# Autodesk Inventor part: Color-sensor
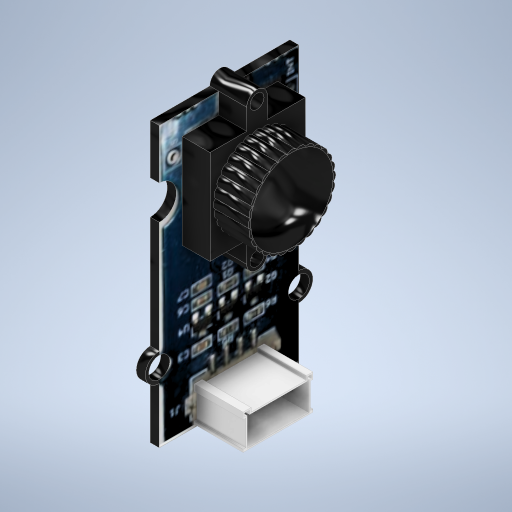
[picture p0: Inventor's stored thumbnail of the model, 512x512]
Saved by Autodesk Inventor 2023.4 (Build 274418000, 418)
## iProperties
Created: 2022-12
Part Number: Color-sensor
Material: Générique
Document SubType Name: Modeling
Designer: ecuenot
Density: 1 g/cm^3
Appearance: Noir
Author: ecuenot
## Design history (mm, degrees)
sketch "Esquisse1" dims "d48" = 3
  geometry: L1 (40, 0)-(40, -20); L2 (0, -20)-(0, 0); L3 (11.5, 0)-(12, 0); L4 (10, 0)-(8, 0); L5 (0, 0)-(8, 0); L6 (11.5, 0)-(40, 0); L7 (40, -20)-(12, -20); L8 (8, -20)-(0, -20); C1 r 1.5 at (10, -20); A1 r 2 centre (10, 0) between (12, 0) and (8, 0); A2 r 2 centre (10, -20) between (8, -20) and (12, -20); 2 further points
  constraints: 16 end point, 5 parallel, 4 point on circle, 3 centre point, 2 coincident, 2 horizontal, 2 perpendicular, 1 horizontal alignment, 2 other
  dimensions: "d0" = 40 distance of L1.end L2.start; "d1" = 20 distance of L1.start L1.end
extrude "Extrusion1" new body sketch "Esquisse1" distance "d9" = 1.3; taper "d10" = 0 deg
sketch "Esquisse15"
  geometry: L1 (0, 0)-(20, 0) reference; L2 (0, 40)-(0, 12) reference; C1 r 2.396 at (10, 0); C2 r 2.429 at (0, 30.425); C3 r 2.696 at (20, 30.425)
  constraints: 3 centre point, 1 midpoint, 1 point on line
extrude "Extrusion11" cut sketch "Esquisse15" distance "d105" = 5; taper "d106" = 0 deg
sketch "Esquisse21"
  geometry: L1 (-20, 40)-(0, 40) reference; C1 r 1 at (-10, 40); C2 r 1.474 at (-10, 40); 5 further points
  constraints: 2 centre point, 1 coincident, 1 midpoint
  dimensions: "d151" = 2 diameter of C1
extrude "Extrusion15" join sketch "Esquisse21" stored distance "d152" = 2; taper "d153" = 0 deg
sketch "Esquisse27"
  geometry: L1 (8.526, 40)-(0, 40) reference; L2 (0, 40)-(19.909, 39.986); L3 (19.909, 39.986)-(19.88, 0); L4 (19.88, 0)-(-0.029, 0.014); L5 (-0.029, 0.014)-(0, 40); 1 further point; 1 other entity
  constraints: 2 other
feature "Décalcomanie3" sketch "Esquisse27"
sketch "Esquisse28"
  geometry: L1 (0.669, -0.155)-(-20.118, -0.155); L2 (-20.118, -0.155)-(-20.118, 40.904); L3 (-20.118, 40.904)-(0.669, 40.904); L4 (0.669, 40.904)-(0.669, -0.155); 1 further point; 1 other entity
  constraints: 2 other
feature "Décalcomanie4" sketch "Esquisse28"
sketch "Esquisse29"
  geometry: L1 (19.5, 39.5)-(0.5, 39.5) reference; L2 (10, 39.5)-(10, 0); L3 (16.953, 37.016)-(3.264, 37.016); L4 (3.264, 37.016)-(3.264, 23.502); L5 (3.264, 23.502)-(16.953, 23.502); L6 (16.953, 23.502)-(16.953, 37.016); L7 (11.474, 37.016)-(8.526, 37.016); L8 (8.526, 37.016)-(8.526, 39.5); L9 (8.526, 39.5)-(11.474, 39.5); L10 (11.474, 39.5)-(11.474, 37.016); L11 (11.474, 39.5)-(11.474, 40); L12 (8.526, 39.5)-(8.526, 40); L13 (11, 40)-(9, 40) reference; L14 (10, 30.259)-(14.396, 30.259); L15 (11.474, 21.018)-(11.474, 23.502); L16 (11.474, 21.018)-(11.474, 20.518); L17 (8.526, 21.018)-(8.526, 20.518); L18 (8.526, 23.502)-(8.526, 21.018); L19 (11.474, 23.502)-(8.526, 23.502); C1 r 5.901 at (10, 30.259); C2 r 1 at (10, 20.518); A1 r 2.396 centre (10, 0) between (12.396, 0) and (7.604, 0) reference; A2 r 1.474 centre (10, 40) between (11.474, 40) and (8.526, 40) reference; A3 r 1.474 centre (10, 40) between (11.474, 40) and (8.526, 40) reference; A4 r 1.474 centre (10, 20.518) between (8.526, 20.518) and (11.474, 20.518); 4 further points
  constraints: 34 end point, 8 symmetric about line, 4 parallel, 3 centre point, 3 horizontal, 3 perpendicular, 3 point on line, 3 vertical, 2 coincident, 2 horizontal alignment, 2 point on circle, 1 midpoint, 6 other
extrude "Extrusion20" join sketch "Esquisse29" distance "d204" = 4; taper "d205" = 0 deg
sketch "Esquisse30"
  geometry: L1 (10, 30.259)-(15.901, 30.259); L2 (15.901, 30.259)-(16.279, 30.259); C1 r 5.901 at (10, 30.259) reference; A1 r 0.858 centre (15.421, 30.259) between (16.279, 30.259) and (15.954, 30.932); A2 r 0.858 centre (15.421, 30.259) between (15.954, 29.586) and (16.279, 30.259); A3 r 0.858 centre (15.285, 31.465) between (15.954, 30.928) and (16.122, 31.656); A4 r 0.858 centre (15.285, 31.465) between (16.122, 31.656) and (15.655, 32.24); A5 r 0.858 centre (14.884, 32.611) between (15.656, 32.236) and (15.658, 32.984); A6 r 0.858 centre (14.884, 32.611) between (15.658, 32.984) and (15.072, 33.449); A7 r 0.858 centre (14.238, 33.639) between (15.074, 33.445) and (14.909, 34.174); A8 r 0.858 centre (14.238, 33.639) between (14.909, 34.174) and (14.235, 34.497); A9 r 0.858 centre (13.38, 34.497) between (14.238, 34.494) and (13.915, 35.168); A10 r 0.858 centre (13.38, 34.497) between (13.915, 35.168) and (13.186, 35.333); A11 r 0.858 centre (12.352, 35.143) between (13.19, 35.331) and (12.725, 35.917); A12 r 0.858 centre (12.352, 35.143) between (12.725, 35.917) and (11.977, 35.915); A13 r 0.858 centre (11.206, 35.544) between (11.981, 35.914) and (11.397, 36.381); A14 r 0.858 centre (11.206, 35.544) between (11.397, 36.381) and (10.669, 36.213); A15 r 0.858 centre (10, 35.68) between (10.673, 36.213) and (10, 36.538); A16 r 0.858 centre (10, 35.68) between (10, 36.538) and (9.327, 36.213); A17 r 0.858 centre (8.794, 35.544) between (9.331, 36.213) and (8.603, 36.381); A18 r 0.858 centre (8.794, 35.544) between (8.603, 36.381) and (8.019, 35.914); A19 r 0.858 centre (7.648, 35.143) between (8.023, 35.915) and (7.275, 35.917); A20 r 0.858 centre (7.648, 35.143) between (7.275, 35.917) and (6.81, 35.331); A21 r 0.858 centre (6.62, 34.497) between (6.814, 35.333) and (6.085, 35.168); A22 r 0.858 centre (6.62, 34.497) between (6.085, 35.168) and (5.762, 34.494); A23 r 0.858 centre (5.762, 33.639) between (5.765, 34.497) and (5.091, 34.174); A24 r 0.858 centre (5.762, 33.639) between (5.091, 34.174) and (4.926, 33.445); A25 r 0.858 centre (5.116, 32.611) between (4.928, 33.449) and (4.342, 32.984); A26 r 0.858 centre (5.116, 32.611) between (4.342, 32.984) and (4.344, 32.236); A27 r 0.858 centre (4.715, 31.465) between (4.345, 32.24) and (3.878, 31.656); A28 r 0.858 centre (4.715, 31.465) between (3.878, 31.656) and (4.046, 30.928); A29 r 0.858 centre (4.579, 30.259) between (4.046, 30.932) and (3.721, 30.259); A30 r 0.858 centre (4.579, 30.259) between (3.721, 30.259) and (4.046, 29.586); A31 r 0.858 centre (4.715, 29.053) between (4.046, 29.59) and (3.878, 28.862); A32 r 0.858 centre (4.715, 29.053) between (3.878, 28.862) and (4.345, 28.278); A33 r 0.858 centre (5.116, 27.907) between (4.344, 28.282) and (4.342, 27.534); A34 r 0.858 centre (5.116, 27.907) between (4.342, 27.534) and (4.928, 27.069); A35 r 0.858 centre (5.762, 26.879) between (4.926, 27.073) and (5.091, 26.344); A36 r 0.858 centre (5.762, 26.879) between (5.091, 26.344) and (5.765, 26.021); A37 r 0.858 centre (6.62, 26.021) between (5.762, 26.024) and (6.085, 25.35); A38 r 0.858 centre (6.62, 26.021) between (6.085, 25.35) and (6.814, 25.185); A39 r 0.858 centre (7.648, 25.375) between (6.81, 25.187) and (7.275, 24.601); A40 r 0.858 centre (7.648, 25.375) between (7.275, 24.601) and (8.023, 24.603); A41 r 0.858 centre (8.794, 24.974) between (8.019, 24.604) and (8.603, 24.137); A42 r 0.858 centre (8.794, 24.974) between (8.603, 24.137) and (9.331, 24.305); A43 r 0.858 centre (10, 24.838) between (9.327, 24.305) and (10, 23.98); A44 r 0.858 centre (10, 24.838) between (10, 23.98) and (10.673, 24.305); A45 r 0.858 centre (11.206, 24.974) between (10.669, 24.305) and (11.397, 24.137); A46 r 0.858 centre (11.206, 24.974) between (11.397, 24.137) and (11.981, 24.604); A47 r 0.858 centre (12.352, 25.375) between (11.977, 24.603) and (12.725, 24.601); A48 r 0.858 centre (12.352, 25.375) between (12.725, 24.601) and (13.19, 25.187); A49 r 0.858 centre (13.38, 26.021) between (13.186, 25.185) and (13.915, 25.35); A50 r 0.858 centre (13.38, 26.021) between (13.915, 25.35) and (14.238, 26.024); A51 r 0.858 centre (14.238, 26.879) between (14.235, 26.021) and (14.909, 26.344); A52 r 0.858 centre (14.238, 26.879) between (14.909, 26.344) and (15.074, 27.073); A53 r 0.858 centre (14.884, 27.907) between (15.072, 27.069) and (15.658, 27.534); A54 r 0.858 centre (14.884, 27.907) between (15.658, 27.534) and (15.656, 28.282); A55 r 0.858 centre (15.285, 29.053) between (15.655, 28.278) and (16.122, 28.862); A56 r 0.858 centre (15.285, 29.053) between (16.122, 28.862) and (15.954, 29.59); 86 further points
  constraints: 112 point on circle, 56 centre point, 4 end point, 2 symmetric about line, 1 coincident, 1 concentric, 1 horizontal, 1 horizontal alignment, 1 point on line, 202 other
  dimensions: "d208" = 360 deg dimension on L1.start A2.centre (derived)
extrude "Extrusion21" join sketch "Esquisse30" distance "d210" = 5; taper "d211" = 0 deg
sketch "Esquisse31"
  geometry: L1 (15, 0.437)-(5, 0.437); L2 (14.043, 4.876)-(6.146, 4.876); L3 (6.146, 4.876)-(6.146, 5.437); L4 (14.043, 5.437)-(14.043, 4.876); L5 (5, 5.437)-(6.146, 5.437); L6 (14.043, 5.437)-(15, 5.437); L7 (15.188, 0.842)-(14.665, 0.842); L8 (14.665, 0.842)-(14.665, 4.504); L9 (14.665, 4.504)-(15.188, 4.504); L10 (5.373, 0.842)-(4.801, 0.842); L11 (4.801, 4.504)-(5.373, 4.504); L12 (5.373, 4.504)-(5.373, 0.842); L13 (5, 0.437)-(5, 0.842); L14 (5, 4.504)-(5, 5.437); L15 (15, 5.437)-(15, 4.504); L16 (15, 0.842)-(15, 0.437); A1 r 2.396 centre (10, 0) between (12.396, 0) and (7.604, 0) reference; 3 further points
  constraints: 32 end point, 9 parallel, 6 point on line, 4 horizontal, 4 perpendicular
  dimensions: "d212" = 5 distance of L1.end L5.start
extrude "Extrusion22" join sketch "Esquisse31" distance "d221" = 7; taper "d222" = 0 deg
sketch "Esquisse33"
  geometry: L1 (5, 5.437)-(5, 4.504) reference; L2 (5, 4.504)-(5.373, 4.504) reference; L3 (5.373, 4.504)-(5.373, 0.842) reference; L4 (5.373, 0.842)-(5, 0.842) reference; L5 (5, 0.842)-(5, 0.437) reference; L6 (5, 0.437)-(15, 0.437) reference; L7 (15, 0.437)-(15, 0.842) reference; L8 (15, 0.842)-(14.665, 0.842) reference; L9 (14.665, 0.842)-(14.665, 4.504) reference; L10 (14.665, 4.504)-(15, 4.504) reference; L11 (15, 4.504)-(15, 5.437) reference; L12 (15, 5.437)-(14.043, 5.437) reference; L13 (14.043, 5.437)-(14.043, 4.876) reference; L14 (14.043, 4.876)-(6.146, 4.876) reference; L15 (6.146, 4.876)-(6.146, 5.437) reference; L16 (6.146, 5.437)-(5, 5.437) reference; L17 (14.443, 0.659)-(5.594, 0.659); L18 (5.594, 0.659)-(5.594, 4.726); L19 (5.594, 4.726)-(5.221, 4.726); L20 (5.221, 4.726)-(5.221, 5.216); L21 (5.221, 5.216)-(5.925, 5.216); L22 (5.925, 5.216)-(5.925, 4.655); L23 (5.925, 4.655)-(14.264, 4.655); L24 (14.264, 4.655)-(14.264, 5.216); L25 (14.264, 5.216)-(14.779, 5.216); L26 (14.779, 5.216)-(14.779, 4.726); L27 (14.779, 4.726)-(14.443, 4.726); L28 (14.443, 4.726)-(14.443, 0.659); 1 further point
  constraints: 24 end point, 11 other
extrude "Extrusion24" cut sketch "Esquisse33" distance "d226" = 6; taper "d227" = 0 deg
node "Solide1"
node "Image8"
node "Image10"
node "Boucle projetée2"
other parameters: "d213" = 5, "d214" = 5
